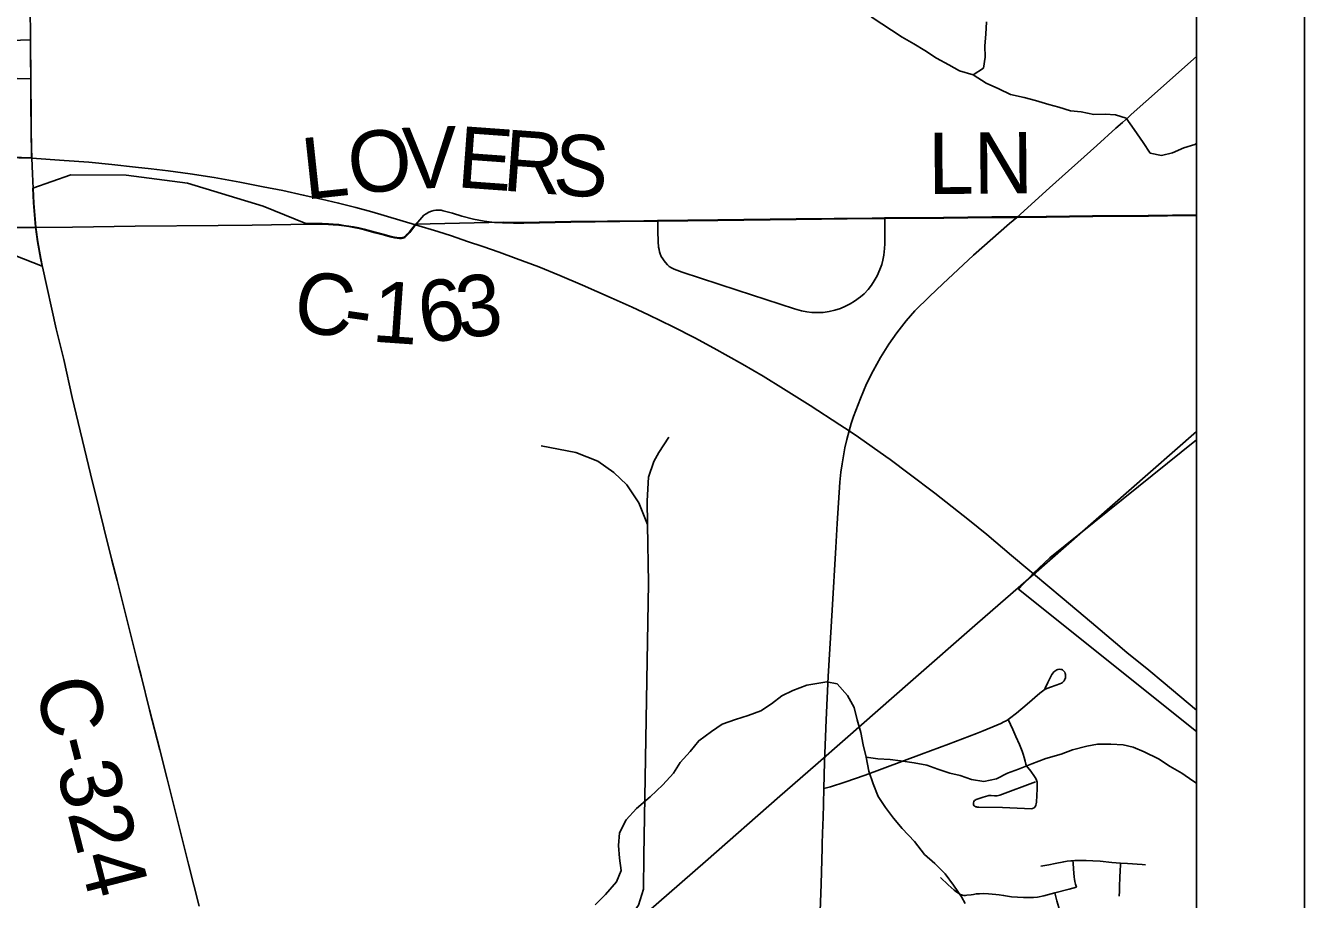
# Model space of a CAD drawing. Extents: x 0 to 34, y 0 to 22.
# Drawn here: x 7.83 to 9.014, y 14.978 to 15.787 of the extents above; entities that cross this region are included whole.
import ezdxf

# ---------------------------------------------------------------- set-up
doc = ezdxf.new("R2010")
doc.units = 0
for name, color, linetype in [('GM_X_City_Street', 7, 'Continuous'), ('GM_X_Corporation', 7, 'Continuous'), ('GM_X_County_Road', 7, 'Continuous'), ('GM_X_County_Road_Text', 7, 'Continuous'), ('GM_X_Minor_River', 7, 'Continuous'), ('GM_X_Rail_Line', 7, 'Continuous'), ('GM_X_State_Route', 7, 'Continuous'), ('SH_Data', 7, 'Continuous')]:
    doc.layers.add(name, color=color, linetype=linetype)

msp = doc.modelspace()

# ---------------------------------------------------------------- linework, layer by layer
at = {"layer": 'GM_X_City_Street'}
for points in [[(7.5544, 15.7316), (7.6053, 15.7318), (7.6327, 15.7324), (7.6625, 15.733), (7.6916, 15.733), (7.7072, 15.733), (7.7295, 15.7336), (7.7382, 15.7344), (7.7634, 15.738), (7.7726, 15.7389), (7.7819, 15.7391), (7.7997, 15.7387), (7.8223, 15.7382), (7.8351, 15.7379)], [(8.4155, 15.606), (8.4156, 15.5968), (8.4158, 15.5871), (8.4162, 15.5821), (8.4166, 15.5797), (8.417, 15.5778), (8.4176, 15.5759), (8.4187, 15.5735), (8.42, 15.5711), (8.4213, 15.5693), (8.4226, 15.5677), (8.4244, 15.5657), (8.4261, 15.5642), (8.4281, 15.5628), (8.4305, 15.5615), (8.4379, 15.5588), (8.4889, 15.5423), (8.542, 15.525), (8.5485, 15.5231), (8.5533, 15.5222), (8.5582, 15.5216), (8.5637, 15.5214), (8.5686, 15.5216), (8.574, 15.5224), (8.5794, 15.5236), (8.5847, 15.5253), (8.5892, 15.5272), (8.5936, 15.5294), (8.5977, 15.532), (8.6032, 15.5359), (8.6064, 15.5388), (8.6101, 15.5428), (8.6132, 15.5467), (8.6159, 15.5507), (8.6186, 15.5556), (8.6211, 15.5612), (8.6227, 15.5658), (8.6238, 15.5699), (8.6246, 15.5747), (8.6253, 15.5809), (8.6255, 15.585), (8.6255, 15.5889), (8.6255, 15.6001), (8.6256, 15.6085)], [(8.5693, 15.0805), (8.5754, 15.0822), (8.5887, 15.0864), (8.6074, 15.0929), (8.6595, 15.1123), (8.6845, 15.1218), (8.7105, 15.1316), (8.7167, 15.134), (8.7292, 15.1391), (8.7331, 15.1409), (8.7359, 15.1422), (8.7379, 15.1433), (8.7398, 15.1446), (8.741, 15.1454), (8.7474, 15.1503), (8.7573, 15.1588), (8.769, 15.1689), (8.7742, 15.1725), (8.7765, 15.1736), (8.779, 15.1746), (8.7841, 15.1763), (8.7877, 15.1776), (8.7893, 15.1783), (8.7902, 15.1789), (8.791, 15.1796), (8.7915, 15.1803), (8.792, 15.1811), (8.7924, 15.1819), (8.7928, 15.1828), (8.793, 15.184), (8.793, 15.1852), (8.7929, 15.1861), (8.7926, 15.1871), (8.7921, 15.1882), (8.7914, 15.1892), (8.7907, 15.1899), (8.7901, 15.1904), (8.7895, 15.1907), (8.7884, 15.1909), (8.7872, 15.1911), (8.7858, 15.1909), (8.7849, 15.1906), (8.7838, 15.19), (8.783, 15.1894), (8.7821, 15.1886), (8.7813, 15.1877), (8.7803, 15.1862), (8.7764, 15.1789), (8.7736, 15.1728)], [(8.7652, 15.0867), (8.732, 15.0744), (8.7296, 15.0738), (8.7285, 15.0737), (8.7271, 15.0738), (8.724, 15.0741), (8.722, 15.074), (8.7209, 15.0738), (8.7168, 15.0725), (8.7103, 15.0704), (8.7092, 15.0699), (8.7087, 15.0694), (8.708, 15.0684), (8.7076, 15.0673), (8.7076, 15.0666), (8.7078, 15.0654), (8.7084, 15.0646), (8.709, 15.0641), (8.7097, 15.0637), (8.7104, 15.0635), (8.7112, 15.0633), (8.7125, 15.0633), (8.7345, 15.063), (8.755, 15.062), (8.761, 15.0619), (8.7624, 15.062), (8.7638, 15.0628), (8.7644, 15.0634), (8.765, 15.0641), (8.7653, 15.065), (8.7657, 15.0665), (8.766, 15.068), (8.7667, 15.0804), (8.7667, 15.0848), (8.7666, 15.0865), (8.766, 15.0884), (8.7655, 15.0898), (8.7643, 15.0917), (8.7607, 15.0967), (8.758, 15.1001), (8.7569, 15.1016), (8.7563, 15.103), (8.7555, 15.1059), (8.7546, 15.1094), (8.7537, 15.1123), (8.7527, 15.1151), (8.7502, 15.1212), (8.7468, 15.1289), (8.7442, 15.1351), (8.742, 15.1399), (8.7398, 15.1446)], [(8.7699, 15.0086), (8.7774, 15.01), (8.7832, 15.0111), (8.7912, 15.0127), (8.7944, 15.0132), (8.7978, 15.0136), (8.7998, 15.0137), (8.8015, 15.0138), (8.8119, 15.0139), (8.8182, 15.0136), (8.8249, 15.0132), (8.8357, 15.0122), (8.8439, 15.0115), (8.8504, 15.0111), (8.8638, 15.0102), (8.8669, 15.01)], [(8.803, 14.9891), (8.8021, 14.992), (8.8016, 14.9944), (8.8011, 14.9967), (8.8009, 14.9986), (8.8005, 15.0024), (8.8003, 15.006), (8.7999, 15.0118), (8.7998, 15.0137)], [(8.8427, 14.9809), (8.8429, 14.9855), (8.843, 14.9906), (8.8432, 14.9974), (8.8436, 15.0054), (8.8438, 15.0091), (8.8439, 15.0115)], [(8.6773, 14.9982), (8.6842, 14.9915), (8.6899, 14.9864), (8.6924, 14.9845), (8.694, 14.9833), (8.6957, 14.9824), (8.6974, 14.9819), (8.6987, 14.9816), (8.7002, 14.9816), (8.7016, 14.9817), (8.7056, 14.9822), (8.7077, 14.9825), (8.7103, 14.9829), (8.7134, 14.9831), (8.7169, 14.9832), (8.7216, 14.9829), (8.7283, 14.9824), (8.7314, 14.9821), (8.7355, 14.9816), (8.7428, 14.9802)], [(8.7428, 14.9802), (8.754, 14.9796), (8.7573, 14.9795), (8.7603, 14.9795), (8.7632, 14.9796), (8.767, 14.98), (8.7729, 14.9812), (8.7831, 14.9839), (8.7964, 14.9874), (8.803, 14.9891)], [(8.7909, 14.9104), (8.791, 14.9138), (8.7912, 14.9208), (8.7915, 14.9295), (8.7915, 14.9354), (8.7913, 14.9408), (8.7912, 14.944), (8.7908, 14.9484), (8.7902, 14.9533), (8.7883, 14.9632), (8.7866, 14.9705), (8.785, 14.9766), (8.7831, 14.9839)]]:
    msp.add_lwpolyline(points, dxfattribs=at)
at = {"layer": 'GM_X_Corporation'}
for points in [[(5.0539, 13.8173), (8.914, 13.8173), (8.914, 17.2449), (8.8621, 17.2445), (8.8285, 17.2444), (8.762, 17.244), (8.6974, 17.2434), (8.6851, 17.2432), (8.6445, 17.2426), (8.5818, 17.2419), (8.5289, 17.2412), (8.4823, 17.2409), (8.4071, 17.2399), (8.3164, 17.2393), (8.2474, 17.2382), (8.2138, 17.2377), (8.1597, 17.237), (8.1363, 17.2369), (8.0417, 17.237), (8.015, 17.2365), (7.9908, 17.2361), (7.8566, 17.2348), (7.8362, 17.2347), (7.6782, 17.2342)], [(7.7884, 15.6662), (7.8358, 15.6648), (7.8347, 15.7739), (7.7786, 15.7722)], [(8.914, 13.8173), (8.914, 15.1333), (8.7495, 15.2653), (8.7631, 15.2799), (8.7784, 15.2941), (8.914, 15.4034), (8.914, 15.6119), (8.8694, 15.6114), (8.8179, 15.6109), (8.7751, 15.6104), (8.7475, 15.6102), (8.7246, 15.61), (8.6799, 15.6096), (8.6254, 15.6091), (8.6139, 15.609), (8.5434, 15.6083), (8.4709, 15.6072), (8.4153, 15.6066), (8.4026, 15.6065), (8.3349, 15.6059), (8.2911, 15.6047), (8.2817, 15.6049), (8.273, 15.605), (8.2726, 15.6051), (8.1911, 15.6032), (8.1857, 15.5962), (8.1836, 15.5939), (8.1818, 15.5922), (8.181, 15.5916), (8.1801, 15.5911), (8.1791, 15.5908), (8.178, 15.5906), (8.1771, 15.5905), (8.176, 15.5906), (8.174, 15.5908), (8.1716, 15.5912), (8.1674, 15.5922), (8.1622, 15.5936), (8.1537, 15.5959), (8.1438, 15.5986), (8.1387, 15.5998), (8.1339, 15.6008), (8.1292, 15.6016), (8.1248, 15.6022), (8.1201, 15.6029), (8.1149, 15.6033), (8.1105, 15.6036), (8.1048, 15.6039), (8.0981, 15.604), (8.0898, 15.6038), (8.05, 15.6201), (7.9802, 15.6414), (7.9233, 15.6486), (7.8721, 15.6489), (7.837, 15.6367), (7.8376, 15.6234), (7.8395, 15.6009), (7.8414, 15.5874), (7.844, 15.5719), (7.8456, 15.5645), (7.7674, 15.5949)]]:
    msp.add_lwpolyline(points, dxfattribs=at)
at = {"layer": 'GM_X_County_Road'}
for p, q in [((8.9048, 15.6112), (8.914, 15.6113)), ((7.9149, 15.2732), (7.9102, 15.292)), ((7.9344, 15.1954), (7.9149, 15.2732))]:
    msp.add_line(p, q, dxfattribs=at)
for points in [[(7.8372, 15.6362), (7.8365, 15.6498), (7.836, 15.6643)], [(7.8397, 15.6003), (7.8379, 15.6228), (7.8372, 15.6362)], [(8.1913, 15.6027), (8.1951, 15.6074), (8.1969, 15.6096), (8.1989, 15.6116), (8.2011, 15.613), (8.2035, 15.6143), (8.206, 15.6152), (8.2082, 15.6159), (8.2101, 15.6162), (8.2115, 15.6164), (8.2129, 15.6164), (8.2149, 15.6162), (8.2167, 15.6158), (8.2253, 15.6134), (8.234, 15.6108), (8.2449, 15.6079), (8.2547, 15.6062), (8.2643, 15.605), (8.2718, 15.6046)], [(7.8397, 15.6003), (7.8738, 15.6006), (7.9316, 15.6015), (8.0084, 15.602), (8.04, 15.6023), (8.0758, 15.603), (8.0891, 15.6032)], [(8.0891, 15.6032), (8.09, 15.6032), (8.0983, 15.6034), (8.1051, 15.6033), (8.1107, 15.6031), (8.1151, 15.6028), (8.1203, 15.6023), (8.125, 15.6017), (8.1294, 15.601), (8.1341, 15.6002), (8.1389, 15.5992), (8.144, 15.598), (8.1539, 15.5953), (8.1624, 15.593), (8.1676, 15.5916), (8.1718, 15.5906), (8.1742, 15.5902), (8.1762, 15.59), (8.1773, 15.5899), (8.1782, 15.59), (8.1793, 15.5902), (8.1803, 15.5906), (8.1812, 15.5911), (8.182, 15.5916), (8.1838, 15.5933), (8.1859, 15.5957), (8.1913, 15.6027)], [(8.2718, 15.6046), (8.2728, 15.6045), (8.2819, 15.6043), (8.2913, 15.6041), (8.3351, 15.6053), (8.4028, 15.606), (8.4155, 15.606)], [(8.4155, 15.606), (8.4711, 15.6067), (8.5436, 15.6077), (8.6141, 15.6084), (8.6256, 15.6085)], [(8.6256, 15.6085), (8.6801, 15.609), (8.7248, 15.6094), (8.7477, 15.6096)], [(8.7477, 15.6096), (8.7753, 15.6099), (8.8181, 15.6103), (8.8696, 15.6108), (8.9048, 15.6112)], [(7.7904, 15.6001), (7.7973, 15.6001), (7.8271, 15.6002), (7.8397, 15.6003)], [(7.8456, 15.5649), (7.8442, 15.5714), (7.8416, 15.5868), (7.8397, 15.6003)], [(7.9102, 15.292), (7.9027, 15.322), (7.8982, 15.3395), (7.8902, 15.3721), (7.8734, 15.4429), (7.8655, 15.4781), (7.8586, 15.5065), (7.8458, 15.5639), (7.8456, 15.5649)], [(7.9544, 15.1163), (7.945, 15.1535), (7.9371, 15.185), (7.9344, 15.1954)], [(7.9762, 15.0302), (7.9713, 15.0499), (7.9614, 15.0894), (7.9544, 15.1163)], [(7.991, 14.9716), (7.9811, 15.0104), (7.9762, 15.0302)]]:
    msp.add_lwpolyline(points, dxfattribs=at)
at = {"layer": 'GM_X_Minor_River'}
for points in [[(8.914, 15.6781), (8.9125, 15.6772), (8.9023, 15.6741), (8.8918, 15.6694), (8.8816, 15.667), (8.8713, 15.6692), (8.8648, 15.679), (8.8563, 15.691), (8.849, 15.7015), (8.8391, 15.7045), (8.8296, 15.7051), (8.819, 15.705), (8.8073, 15.7075), (8.7974, 15.7082), (8.7868, 15.7118), (8.7773, 15.714), (8.7651, 15.718), (8.7545, 15.7206), (8.7419, 15.7235), (8.7313, 15.7286), (8.7195, 15.7338), (8.7073, 15.7417), (8.6947, 15.7453), (8.6848, 15.7509), (8.6734, 15.7572), (8.6627, 15.7643), (8.6524, 15.7702), (8.6417, 15.7766), (8.6131, 15.7952)], [(8.7073, 15.7417), (8.717, 15.7478), (8.7184, 15.7581), (8.7183, 15.7684), (8.719, 15.7794), (8.7196, 15.7908)], [(8.3576, 14.9729), (8.367, 14.9825), (8.3771, 14.994), (8.3815, 15.0047), (8.3799, 15.0161), (8.379, 15.0279), (8.38, 15.0396), (8.3863, 15.0515), (8.3957, 15.0622), (8.4084, 15.073), (8.42, 15.0841), (8.4301, 15.0949), (8.4361, 15.1048), (8.4454, 15.1148), (8.4533, 15.1248), (8.4653, 15.1333), (8.4751, 15.1402), (8.4875, 15.1445), (8.4992, 15.1481), (8.5109, 15.1524), (8.5207, 15.159), (8.5304, 15.1663), (8.5406, 15.1714), (8.5534, 15.1764), (8.572, 15.1793), (8.5815, 15.1775), (8.591, 15.1666), (8.5972, 15.1557), (8.6, 15.1443), (8.6035, 15.1326), (8.6056, 15.1209), (8.6083, 15.1095), (8.6108, 15.0966), (8.6147, 15.0849), (8.6194, 15.0732), (8.6263, 15.063), (8.6336, 15.0532), (8.6417, 15.0434), (8.6532, 15.0314), (8.6624, 15.0194), (8.6719, 15.0111), (8.6815, 15.0014), (8.6892, 14.9912), (8.6965, 14.9803), (8.7001, 14.974)], [(8.6083, 15.1095), (8.619, 15.1081), (8.6307, 15.1075), (8.6402, 15.1061), (8.6527, 15.1043), (8.6645, 15.1022), (8.6747, 15.0985), (8.6858, 15.0948), (8.6953, 15.0927), (8.7059, 15.089), (8.7173, 15.0872), (8.729, 15.0896), (8.7392, 15.0947), (8.7494, 15.0986), (8.7618, 15.1033), (8.7746, 15.1084), (8.789, 15.1124), (8.7995, 15.1163), (8.8127, 15.1199), (8.8226, 15.1215), (8.8347, 15.1216), (8.8461, 15.121), (8.8555, 15.1188), (8.8658, 15.1144), (8.8791, 15.1081), (8.8898, 15.101), (8.9005, 15.0947), (8.9108, 15.0876), (8.914, 15.0856)]]:
    msp.add_lwpolyline(points, dxfattribs=at)
at = {"layer": 'GM_X_Rail_Line'}
for points in [[(8.406, 15.3252), (8.4057, 15.347), (8.4069, 15.3689), (8.4119, 15.3834), (8.4163, 15.3917), (8.4257, 15.4059)], [(8.5613, 15.1022), (8.5889, 15.1264), (8.6494, 15.1794), (8.7115, 15.2338), (8.7631, 15.2787), (8.8516, 15.3564), (8.914, 15.4112)], [(8.406, 15.3252), (8.398, 15.3451), (8.3869, 15.362), (8.3749, 15.3733), (8.3598, 15.3838), (8.3396, 15.3917), (8.3076, 15.3979)], [(8.359, 14.9251), (8.3845, 14.9543), (8.3976, 14.9726), (8.4022, 14.9875), (8.4025, 15.0183), (8.4068, 15.2707), (8.406, 15.3252)], [(8.3708, 14.9355), (8.4596, 15.0131), (8.5285, 15.0734), (8.5613, 15.1022)]]:
    msp.add_lwpolyline(points, dxfattribs=at)
at = {"layer": 'GM_X_State_Route'}
msp.add_line((8.7581, 15.2838), (8.7633, 15.2793), dxfattribs=at)
for points in [[(7.8349, 15.7733), (7.8349, 15.7796), (7.8345, 15.8006)], [(7.836, 15.6643), (7.8355, 15.6835), (7.8354, 15.6933), (7.8351, 15.7126), (7.8351, 15.7379), (7.8351, 15.7419), (7.8349, 15.755), (7.8349, 15.7733)], [(8.7477, 15.6096), (8.7781, 15.6369), (8.8219, 15.6763), (8.8395, 15.6921), (8.8455, 15.6975), (8.8511, 15.7024), (8.8538, 15.7049), (8.8672, 15.7168), (8.914, 15.7587)], [(7.7886, 15.6657), (7.7906, 15.6656), (7.8119, 15.6652), (7.836, 15.6643)], [(7.836, 15.6643), (7.8659, 15.6624), (7.8888, 15.6607), (7.91, 15.6587), (7.9319, 15.6562), (7.9465, 15.6545), (7.9621, 15.6526), (7.9825, 15.6499), (8.0047, 15.6464), (8.0286, 15.6421), (8.0501, 15.638), (8.0683, 15.6344), (8.0873, 15.6303), (8.1043, 15.6265), (8.12, 15.6228), (8.136, 15.6188), (8.1507, 15.6148), (8.1913, 15.6027)], [(8.6671, 15.5362), (8.6792, 15.548), (8.7076, 15.5746), (8.7411, 15.6039), (8.7477, 15.6096)], [(8.1913, 15.6027), (8.2117, 15.5965), (8.2245, 15.5924), (8.2393, 15.5874), (8.2535, 15.5827), (8.2685, 15.5774), (8.2844, 15.5716), (8.3053, 15.5637), (8.3247, 15.5559), (8.3457, 15.5468), (8.3724, 15.5351), (8.3917, 15.5264), (8.4069, 15.5193), (8.4298, 15.5081), (8.4498, 15.498), (8.4673, 15.4885), (8.4939, 15.4736), (8.513, 15.4624), (8.5317, 15.4509), (8.5564, 15.4353), (8.584, 15.4173), (8.5926, 15.4118)], [(8.5926, 15.4118), (8.5946, 15.4188), (8.5966, 15.425), (8.603, 15.4418), (8.6088, 15.4554), (8.6148, 15.4675), (8.6217, 15.4799), (8.6292, 15.492), (8.6366, 15.5026), (8.6454, 15.5137), (8.6535, 15.5229), (8.6671, 15.5362)], [(8.5802, 15.3039), (8.5815, 15.3259), (8.5841, 15.3642), (8.585, 15.3735), (8.5861, 15.3813), (8.5873, 15.3887), (8.5887, 15.3962), (8.5904, 15.4038), (8.5926, 15.4118)], [(8.5926, 15.4118), (8.6014, 15.406), (8.6265, 15.3882), (8.6305, 15.3853)], [(8.6305, 15.3853), (8.6481, 15.3722), (8.6718, 15.3541), (8.704, 15.3287), (8.72, 15.3159), (8.743, 15.2965), (8.7581, 15.2838)], [(8.5656, 14.9586), (8.5666, 14.9921), (8.5676, 15.0257), (8.5676, 15.03), (8.5681, 15.0473), (8.5684, 15.0535), (8.5689, 15.0665), (8.5693, 15.0805), (8.5699, 15.105), (8.5712, 15.1441), (8.5732, 15.1844), (8.5769, 15.2459), (8.5802, 15.3039)], [(8.7633, 15.2793), (8.7899, 15.2571), (8.8169, 15.2344), (8.8392, 15.2154), (8.8496, 15.2067), (8.8699, 15.1902), (8.8833, 15.179), (8.914, 15.1531)]]:
    msp.add_lwpolyline(points, dxfattribs=at)
at = {"layer": 'SH_Data'}
for p, q in [((9.014, 20.7173), (9.014, 13.7173)), ((8.914, 20.6173), (8.914, 13.8173))]:
    msp.add_line(p, q, dxfattribs=at)

# ---------------------------------------------------------------- texts
at = {"layer": 'GM_X_County_Road_Text'}
for s, height, rotation, p in [('O', 0.0568, 6.0876, (8.1315, 15.6305)), ('V', 0.0568, 2.1169, (8.1801, 15.6357)), ('E', 0.0568, 355.8478, (8.2285, 15.6376)), ('R', 0.0568, 355.777, (8.2708, 15.6345)), ('S', 0.0568, 355.7816, (8.3174, 15.6311)), ('LN', 0.05682, 0.5134, (8.6659, 15.6311)), ('L', 0.0568, 6.1187, (8.0892, 15.626)), ('C', 0.0568, 351.5862, (8.076, 15.5053)), ('3', 0.0568, 6.8281, (8.232, 15.4973)), ('1', 0.0568, 356.0186, (8.15, 15.4946)), ('6', 0.0568, 7.6538, (8.1975, 15.4926)), ('-', 0.0568, 351.8008, (8.1224, 15.4985)), ('C-324', 0.05682, 284.4392, (7.8383, 15.1765))]:
    msp.add_text(s, height=height, rotation=rotation, dxfattribs=at).set_placement(p)

doc.saveas('drawing.dxf')
